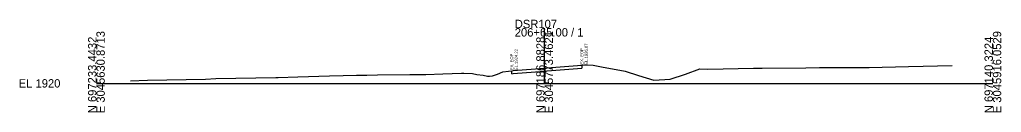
# Model space of a CAD drawing. Extents: x -26 to 19003, y -31 to 24541.
# Drawn here: x 1974.3 to 2302.8, y 13990.3 to 14021.3 of the extents above; entities that cross this region are included whole.
import ezdxf

# ---------------------------------------------------------------- set-up
doc = ezdxf.new("R2010")
doc.units = 0
for name, color, linetype in [('DESIGN - SHEET - Light Grid', 7, 'Continuous'), ('SURVEY - GROUND - Existing Pavement Layer', 7, 'Continuous'), ('SURVEY - GROUND - Existing Pavement Text', 7, 'Continuous'), ('SURVEY - GROUND - Top of Ground', 7, 'Continuous')]:
    doc.layers.add(name, color=color, linetype=linetype)

msp = doc.modelspace()

# ---------------------------------------------------------------- linework, layer by layer
at = {"layer": 'DESIGN - SHEET - Light Grid'}
for p, q in [((2150, 14000), (2150, 14018.46)), ((2000, 14000), (2150, 14000)), ((2150, 14000), (2300, 14000))]:
    msp.add_line(p, q, dxfattribs=at)
at = {"layer": 'SURVEY - GROUND - Existing Pavement Layer'}
for p, q in [((2162.41, 14006.07), (2162.41, 14005.07)), ((2138.98, 14003.22), (2138.98, 14004.22)), ((2138.98, 14003.22), (2139.52, 14003.29)), ((2139.52, 14003.29), (2150, 14004.08)), ((2150, 14004.08), (2150.5, 14004.12)), ((2150.5, 14004.12), (2150.84, 14004.15)), ((2150.84, 14004.15), (2162.41, 14005.07))]:
    msp.add_line(p, q, dxfattribs=at)
at = {"layer": 'SURVEY - GROUND - Top of Ground'}
msp.add_lwpolyline([(2011.46, 14000.9), (2017.08, 14001.02), (2036.54, 14001.44), (2040, 14001.58), (2060.09, 14001.92), (2060.83, 14001.94), (2067.36, 14002.16), (2077.99, 14002.54), (2082.6, 14002.6), (2087.01, 14002.7), (2090.53, 14002.75), (2094.12, 14002.8), (2104.86, 14002.93), (2110.28, 14002.99), (2115.91, 14003.18), (2122.2, 14003.4), (2122.94, 14003.38), (2125.87, 14003.35), (2127.36, 14002.96), (2129.47, 14002.72), (2130.84, 14002.43), (2131.57, 14002.46), (2132.56, 14002.55), (2134.21, 14003.04), (2135.99, 14003.88), (2137.87, 14004.1), (2138.98, 14004.22), (2139.52, 14004.29), (2150, 14005.08), (2150.5, 14005.12), (2150.84, 14005.15), (2162.41, 14006.07), (2163.48, 14006.15), (2166.28, 14006.07), (2169.08, 14005.56), (2176.97, 14004.11), (2181.39, 14002.61), (2186.52, 14001.07), (2191.99, 14001.39), (2197.15, 14003.13), (2201.95, 14004.85), (2204.6, 14004.78), (2219.88, 14005.09), (2222.76, 14005.13), (2237.38, 14005.24), (2241.96, 14005.34), (2258.57, 14005.3), (2271.81, 14005.64), (2286.38, 14005.97)], dxfattribs=at)

# ---------------------------------------------------------------- texts
at = {"layer": 'DESIGN - SHEET - Light Grid'}
for s, p in [('206+65.00 / 1', (2140, 14015.66)), ('DSR107', (2140, 14018.46)), ('EL 1920', (1974, 13998.6))]:
    msp.add_text(s, height=2.8, dxfattribs=at).set_placement(p)
for s, p in [('N 697233.4432', (2000, 13990)), ('E 3045630.8713', (2002.8, 13990)), ('N 697186.8828', (2150, 13990)), ('E 3045773.4621', (2152.8, 13990)), ('N 697140.3224', (2300, 13990)), ('E 3045916.0529', (2302.8, 13990))]:
    msp.add_text(s, height=2.8, rotation=90, dxfattribs=at).set_placement(p)
at = {"layer": 'SURVEY - GROUND - Existing Pavement Text'}
for s, p in [('EL.1926.07', (2164.41, 14006.27)), ('EX. EOP', (2139.48, 14004.42)), ('EL.1924.22', (2140.98, 14004.42)), ('EX. EOP', (2162.91, 14006.27))]:
    msp.add_text(s, height=1, rotation=90, dxfattribs=at).set_placement(p)

doc.saveas('drawing.dxf')
